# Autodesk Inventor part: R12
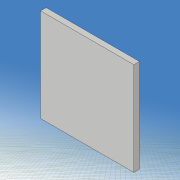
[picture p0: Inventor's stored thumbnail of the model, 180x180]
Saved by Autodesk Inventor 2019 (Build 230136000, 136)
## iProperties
Created: 2021-05
Part Number: R12
Material: 一般
Document SubType Name: Modeling
Designer: kikut
Density: 1 g/cm^3
Appearance: 既定
Mass: 0.0212833 g
Surface Area: 0.889661 cm^2
Volume: 0.0212833 cm^3
Author: kikut
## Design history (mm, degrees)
sketch "スケッチ1"
  geometry: L1 (80, 60)-(-80, 60); L2 (-80, 60)-(-80, -60); L3 (-80, -60)-(80, -60); L4 (80, -60)-(80, 60); L5 (80, 60)-(-80, -60); L6 (-80, 60)-(80, -60); 1 further point
  constraints: 12 end point, 2 midpoint, 2 parallel, 1 horizontal, 1 perpendicular
  dimensions: "d0" = 160 distance of L2.end L3.end; "d1" = 120 distance of L1.end L2.end
extrude "押し出し1" new body sketch "スケッチ1" stored distance "d2" = 0.6; taper "d3" = 0 deg
sketch "スケッチ2"
  geometry: L1 (-140, 0)-(140, 0) reference; L2 (0, -54)-(20, -30); L3 (0, 54)-(20, 30); L4 (0, -3)-(6.514, -3); L5 (6.514, -3)-(16, -6); L6 (16, -6)-(24, -3); L7 (24, -3)-(33.716, -3); L8 (0, 3)-(6.514, 3); L9 (6.514, 3)-(16, 6); L10 (16, 6)-(24, 3); L11 (24, 3)-(33.716, 3); L12 (0, -98)-(0, 98) reference; L13 (-100, -70)-(100, -70); L14 (100, -70)-(100, 70); L15 (100, 70)-(-100, 70); L16 (-100, 70)-(-100, -70); L17 (-100, -70)-(100, 70); L18 (100, -70)-(-100, 70); A1 r 60 centre (54.312, 28.5) between (0, 54) and (0, 3); A2 r 60 centre (54.312, -28.5) between (0, -3) and (0, -54); A3 r 18.111 centre (18, -12) between (20, -30) and (33.716, -3); A4 r 18.111 centre (18, 12) between (33.716, 3) and (20, 30); 1 further point
  constraints: 32 end point, 8 point on circle, 8 symmetric about line, 4 centre point, 3 horizontal, 2 collinear, 2 midpoint, 2 parallel, 1 perpendicular
  dimensions: "d5" = 60 radius of A1; "d6" = 6 distance of L8.start L4.start; "d7" = 108 distance of L3.start L2.start; "d8" = 0 horizontal distance of L3.start L8.start; "d9" = 60 distance of L3.end L2.end; "d10" = 0 horizontal distance of point (0, 0) L3.start; "d11" = 20 horizontal distance of L3.start L3.end; "d12" = 24 distance of A4.centre A3.centre; "d13" = 6 distance of L11.end L7.end; "d14" = 12 distance of L9.end L5.end; "d15" = 16 distance from line of L12 L5.end; "d16" = 24 distance from line of L6.end L12; "d17" = 200 distance of L14.end L15.end; "d18" = 140 distance of L15.end L13.start; "d30" = 18 distance from line of L12 A4.centre
extrude "押し出し2" cut sketch "スケッチ2" stored distance "d19" = 10; taper "d20" = 0 deg
sketch "スケッチ3"
  geometry: L1 (49.705, -17.97)-(33.948, -15.191); L2 (33.948, -15.191)-(34.295, -13.222); L3 (34.295, -13.222)-(50.052, -16); L4 (50.052, -16)-(49.705, -17.97); L5 (49.705, -17.97)-(34.295, -13.222); L6 (33.948, -15.191)-(50.052, -16); L7 (50.052, 16)-(34.295, 13.222); L8 (34.295, 13.222)-(33.948, 15.191); L9 (33.948, 15.191)-(49.705, 17.97); L10 (49.705, 17.97)-(50.052, 16); L11 (50.052, 16)-(33.948, 15.191); L12 (34.295, 13.222)-(49.705, 17.97); L13 (-112, 0)-(112, 0) reference; L14 (0, -84)-(0, 84) reference; 3 further points
  constraints: 24 end point, 4 midpoint, 4 parallel, 2 perpendicular, 2 symmetric about line
  dimensions: "d21" = 2 distance of L3.end L1.start; "d22" = 2 distance of L9.end L7.start; "d23" = 16 distance of L8.end L9.end; "d24" = 42 distance from line of L14 point (42, 15.596); "d26" = 10 deg angle of L7 L13; "d62" = 16 distance from line of L3.end L13
extrude "押し出し3" join sketch "スケッチ3" distance "d27" = 0.6; taper "d28" = 0 deg
fillet "フィレット1" dims "d31" = 2
fillet "フィレット2" dims "d32" = 1
sketch "スケッチ6"
  geometry: L1 (-20, 60)-(80, 60); L2 (80, 60)-(80, -60); L3 (80, -60)-(-20, -60); L4 (-20, -60)-(-20, 60); L5 (-46.168, 0)-(93.832, 0) reference; L6 (0, -84)-(0, 84) reference; L7 (0, 20)-(10, 20); L8 (10, 20)-(10, 30); L9 (10, 30)-(0, 30); L10 (0, 30)-(0, 20); 1 further point
  constraints: 16 end point, 4 parallel, 2 horizontal, 2 perpendicular, 1 other
  dimensions: "d63" = 120 distance of L3.end L1.start; "d64" = 100 distance of L1.start L1.end; "d65" = 20 distance between parallel lines of L6 L4; "d66" = 10 distance of L8.end L9.end; "d73" = 10 distance of L9.end L7.start; "d74" = 20 distance between parallel lines of L7 L5; "d75" = 20 distance between parallel lines of L10 L4
extrude "押し出し4" cut sketch "スケッチ6" stored distance "d70" = 10; taper "d71" = 0 deg
node "ソリッド1"
